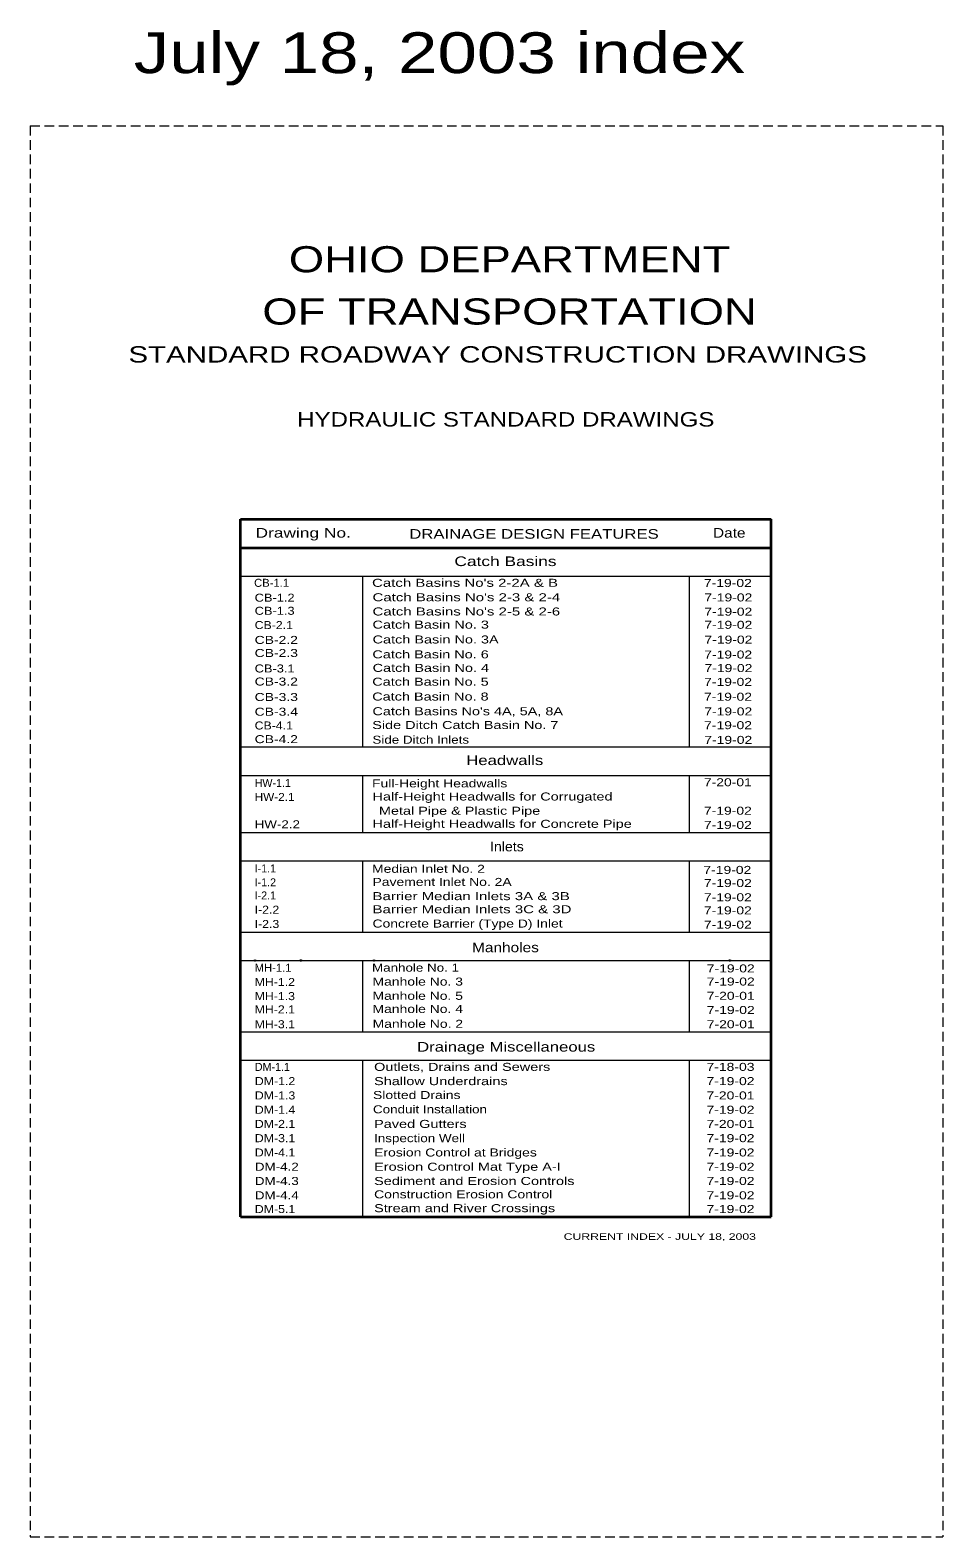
# Model space of a CAD drawing. Extents: x 597.2 to 619.2, y 2097.9 to 2134.2.
import ezdxf
from ezdxf.enums import TextEntityAlignment as Align

# ---------------------------------------------------------------- set-up
doc = ezdxf.new("R2010")
doc.units = 0
doc.header["$LTSCALE"] = 0.077
doc.header["$PDMODE"] = 32
doc.header["$PDSIZE"] = 0.0385
doc.linetypes.add('MEDIUM_DASHED', pattern=[4.5, 3, -1.5])
doc.layers.add('1', color=7, linetype='Continuous', lineweight=13)

msp = doc.modelspace()

# ---------------------------------------------------------------- linework, layer by layer
at = {"layer": '1', "linetype": 'MEDIUM_DASHED'}
for p, q in [((597.168, 2131.89967), (619.168, 2131.89967)), ((597.168, 2131.89967), (597.168, 2097.89967)), ((619.168, 2131.89967), (619.168, 2097.89967)), ((597.168, 2097.89967), (619.168, 2097.89967))]:
    msp.add_line(p, q, dxfattribs=at)
at = {"layer": '1', "lineweight": 35}
for p, q in [((602.237, 2105.61442), (602.237, 2122.41925)), ((602.237, 2122.41925), (615.02575, 2122.41925)), ((615.02575, 2105.61442), (615.02575, 2122.41925)), ((602.23667, 2121.73333), (615.02558, 2121.73333)), ((602.237, 2105.61442), (615.02592, 2105.61442))]:
    msp.add_line(p, q, dxfattribs=at)
at = {"layer": '1'}
for p, q in [((602.23667, 2121.04742), (615.02558, 2121.04742)), ((605.18808, 2116.932), (605.18808, 2121.04742)), ((613.05808, 2116.932), (613.05808, 2121.04742)), ((602.23667, 2116.932), (615.02558, 2116.932)), ((602.23667, 2116.24617), (615.02558, 2116.24617)), ((605.18808, 2114.87225), (605.18808, 2116.24617)), ((613.05808, 2114.87217), (613.05808, 2116.24617)), ((602.23667, 2114.87433), (615.02558, 2114.87433)), ((602.23667, 2114.18842), (615.02558, 2114.18842)), ((602.23667, 2114.18842), (615.02558, 2114.18842)), ((605.18808, 2114.18842), (605.18808, 2114.19175)), ((605.18808, 2112.47275), (605.18808, 2114.18842)), ((613.05808, 2114.18842), (613.05808, 2114.189)), ((613.05808, 2112.47275), (613.05808, 2114.18842)), ((602.23667, 2112.47275), (615.02558, 2112.47275)), ((602.23683, 2111.78683), (615.02558, 2111.78683)), ((605.18808, 2110.07208), (605.18808, 2111.78683)), ((613.05808, 2110.09533), (613.05808, 2111.78683)), ((605.18808, 2110.07208), (605.18808, 2111.10092)), ((613.05808, 2110.07208), (613.05808, 2111.10092)), ((602.23683, 2110.07208), (615.02558, 2110.07208)), ((602.23667, 2109.38617), (615.02558, 2109.38617)), ((605.18808, 2108.01408), (605.18808, 2109.38617)), ((613.05808, 2108.01408), (613.05808, 2109.38617)), ((613.05808, 2106.65533), (613.05808, 2109.36508)), ((605.18808, 2106.11242), (605.18808, 2108.85625)), ((605.18808, 2105.61342), (605.18808, 2106.9855)), ((613.05808, 2105.61342), (613.05808, 2107.00658))]:
    msp.add_line(p, q, dxfattribs=at)
for p in [(602.59033, 2111.78683), (603.69258, 2111.78683), (605.45783, 2111.78683), (614.03458, 2111.78683)]:
    msp.add_point(p, dxfattribs=at)

# ---------------------------------------------------------------- texts
for s, height, width, p in [('July 18, 2003 index', 0.9837, 1.3, (599.66625, 2133.16925)), ('CB-1.1', 0.1928, 1.05, (602.56633, 2120.79133)), ("Catch Basins No's 2-2A & B", 0.1928, 1.4, (605.40933, 2120.79167)), ('7-19-02', 0.1928, 1.3, (613.40775, 2120.78758)), ('CB-1.2', 0.1928, 1.2, (602.57975, 2120.43317)), ("Catch Basins No's 2-3 & 2-4", 0.1928, 1.4, (605.42092, 2120.44383)), ('7-19-02', 0.1928, 1.3, (613.41933, 2120.43975)), ('CB-1.3', 0.1928, 1.2, (602.57975, 2120.11783)), ("Catch Basins No's 2-5 & 2-6", 0.1928, 1.4, (605.42092, 2120.10083)), ('7-19-02', 0.1928, 1.3, (613.41933, 2120.09675)), ('CB-2.1', 0.1928, 1.15, (602.57975, 2119.77392)), ('Catch Basin No. 3', 0.1928, 1.35, (605.42075, 2119.78458)), ('7-19-02', 0.1928, 1.3, (613.41917, 2119.7805)), ('CB-2.2', 0.1928, 1.3, (602.57975, 2119.41575)), ('Catch Basin No. 3A', 0.1928, 1.35, (605.42292, 2119.42642)), ('7-19-02', 0.1928, 1.3, (613.42133, 2119.42233)), ('CB-2.3', 0.1928, 1.3, (602.57975, 2119.10042)), ('Catch Basin No. 6', 0.1928, 1.35, (605.41758, 2119.06808)), ('7-19-02', 0.1928, 1.3, (613.416, 2119.064)), ('CB-3.1', 0.1928, 1.2, (602.57975, 2118.72783)), ('Catch Basin No. 4', 0.1928, 1.35, (605.42358, 2118.74183)), ('7-19-02', 0.1928, 1.3, (613.422, 2118.73775)), ('CB-3.2', 0.1928, 1.3, (602.57975, 2118.41258)), ('Catch Basin No. 5', 0.1928, 1.35, (605.41517, 2118.409)), ('7-19-02', 0.1928, 1.3, (613.41358, 2118.40492)), ('CB-3.3', 0.1928, 1.3, (602.57975, 2118.04)), ('Catch Basin No. 8', 0.1928, 1.35, (605.414, 2118.05142)), ('7-19-02', 0.1928, 1.3, (613.41242, 2118.04733)), ('CB-3.4', 0.1928, 1.3, (602.57975, 2117.68575)), ("Catch Basins No's 4A, 5A, 8A", 0.1928, 1.35, (605.41908, 2117.69717)), ('7-19-02', 0.1928, 1.3, (613.4175, 2117.69308)), ('CB-4.1', 0.1928, 1.15, (602.57975, 2117.35408)), ('Side Ditch Catch Basin No. 7', 0.1928, 1.35, (605.414, 2117.36558)), ('7-19-02', 0.1928, 1.3, (613.41242, 2117.3615)), ('CB-4.2', 0.1928, 1.3, (602.57975, 2117.02458)), ('Side Ditch Inlets', 0.1928, 1.25, (605.41908, 2117.01125)), ('7-19-02', 0.1928, 1.3, (613.4175, 2117.00717)), ('Full-Height Headwalls', 0.1928, 1.3, (605.40933, 2115.95867)), ('7-20-01', 0.1928, 1.3, (613.40775, 2115.98625)), ('HW-2.1', 0.1928, 1.1, (602.57975, 2115.63192)), ('Half-Height Headwalls for Corrugated ', 0.1928, 1.35, (605.42092, 2115.64258)), ('HW-2.2', 0.1928, 1.25, (602.57975, 2114.97367)), ('Half-Height Headwalls for Concrete Pipe', 0.1928, 1.35, (605.42108, 2114.98433)), ('       Metal Pipe & Plastic Pipe', 0.1928, 1.35, (604.8975, 2115.29958)), ('7-19-02', 0.1928, 1.3, (613.40775, 2115.30042)), ('7-19-02', 0.1928, 1.3, (613.40775, 2114.95742)), ('Median Inlet No. 2', 0.1928, 1.3, (605.40933, 2113.901)), ('Pavement Inlet No. 2A', 0.1928, 1.3, (605.42092, 2113.58483)), ('7-19-02', 0.1928, 1.3, (613.396, 2113.87408)), ('7-19-02', 0.1928, 1.3, (613.40758, 2113.55792)), ('Barrier Median Inlets 3A & 3B', 0.1928, 1.4, (605.42092, 2113.24192)), ('7-19-02', 0.1928, 1.3, (613.40758, 2113.215)), ('I-2.2', 0.1928, 1.15, (602.57975, 2112.915)), ('Barrier Median Inlets 3C & 3D', 0.1928, 1.4, (605.42075, 2112.92567)), ('7-19-02', 0.1928, 1.3, (613.40742, 2112.89875)), ('I-2.3', 0.1928, 1.15, (602.57975, 2112.571)), ('Concrete Barrier (Type D) Inlet', 0.1928, 1.3, (605.42075, 2112.58175)), ('7-19-02', 0.1928, 1.3, (613.40742, 2112.55483)), ('MH-1.1', 0.1928, 1.05, (602.57975, 2111.51592)), ('Manhole No. 1', 0.1928, 1.25, (605.40933, 2111.51875)), ('7-19-02', 0.1928, 1.3, (613.47758, 2111.50083)), ('MH-1.2', 0.1928, 1.15, (602.57975, 2111.17258)), ('Manhole No. 3', 0.1928, 1.3, (605.42092, 2111.18325)), ('7-19-02', 0.1928, 1.3, (613.47758, 2111.18408)), ('MH-1.3', 0.1928, 1.15, (602.57975, 2110.83258)), ('Manhole No. 5', 0.1928, 1.3, (605.42092, 2110.84033)), ('7-20-01', 0.1928, 1.3, (613.47758, 2110.84108)), ('MH-2.1', 0.1928, 1.15, (602.57975, 2110.51333)), ('Manhole No. 4', 0.1928, 1.3, (605.42075, 2110.524)), ('7-19-02', 0.1928, 1.3, (613.47758, 2110.49817)), ('MH-3.1', 0.1928, 1.15, (602.57975, 2110.15517)), ('Manhole No. 2', 0.1928, 1.3, (605.42292, 2110.16583)), ('7-20-01', 0.1928, 1.3, (613.47758, 2110.15517)), ('Outlets, Drains and Sewers', 0.1933, 1.35, (605.45875, 2109.12783)), ('7-18-03', 0.1933, 1.3, (613.46958, 2109.12783)), ('DM-1.2', 0.1933, 1.15, (602.58383, 2108.78458)), ('DM-1.3', 0.1933, 1.15, (602.58383, 2108.43967)), ('Slotted Drains', 0.1933, 1.3, (605.43217, 2108.45025)), ('Shallow Underdrains', 0.1933, 1.35, (605.45875, 2108.78458)), ('7-19-02', 0.1933, 1.3, (613.46958, 2108.78458)), ('7-20-01', 0.1933, 1.3, (613.46958, 2108.43967)), ('DM-1.4', 0.1933, 1.15, (602.58383, 2108.09475)), ('Conduit Installation', 0.1933, 1.25, (605.43217, 2108.10533)), ('7-19-02', 0.1933, 1.3, (613.46958, 2108.09475)), ('DM-2.1', 0.1933, 1.15, (602.58383, 2107.75317)), ('Paved Gutters', 0.1933, 1.35, (605.45875, 2107.75317)), ('7-20-01', 0.1933, 1.3, (613.46958, 2107.75317)), ('DM-3.1', 0.1933, 1.15, (602.58383, 2107.40992)), ('Inspection Well', 0.1933, 1.25, (605.45875, 2107.40992)), ('7-19-02', 0.1933, 1.3, (613.46958, 2107.40992)), ('DM-4.1', 0.1933, 1.15, (602.58383, 2107.06492)), ('Erosion Control at Bridges', 0.1933, 1.3, (605.45875, 2107.06492)), ('7-19-02', 0.1933, 1.3, (613.46958, 2107.06492)), ('DM-4.2', 0.1933, 1.25, (602.58383, 2106.72175)), ('Erosion Control Mat Type A-I', 0.1933, 1.35, (605.45875, 2106.72175)), ('7-19-02', 0.1933, 1.3, (613.46958, 2106.72175)), ('DM-4.3', 0.1933, 1.25, (602.58383, 2106.3785)), ('Sediment and Erosion Controls', 0.1933, 1.35, (605.45875, 2106.3785)), ('7-19-02', 0.1933, 1.3, (613.46958, 2106.3785)), ('DM-4.4', 0.1933, 1.25, (602.58383, 2106.0335)), ('Construction Erosion Control', 0.1933, 1.3, (605.45875, 2106.0565)), ('7-19-02', 0.1933, 1.3, (613.46958, 2106.0335)), ('DM-5.1', 0.1933, 1.15, (602.58383, 2105.70208)), ('Stream and River Crossings', 0.1933, 1.35, (605.45875, 2105.72333)), ('7-19-02', 0.1933, 1.3, (613.46958, 2105.70208))]:
    msp.add_text(s, height=height, dxfattribs=dict(at, width=width)).set_placement(p)
for s, height, width, p in [('OHIO DEPARTMENT', 0.6296, 1.3, (608.72371, 2128.36975)), ('OF TRANSPORTATION', 0.6296, 1.3, (608.72383, 2127.11075)), ('STANDARD ROADWAY CONSTRUCTION DRAWINGS', 0.3935, 1.35, (608.43679, 2126.19558)), ('HYDRAULIC STANDARD DRAWINGS', 0.3471, 1.25, (608.63212, 2124.65308)), ('Drawing No.', 0.2314, 1.35, (603.75004, 2121.9765)), ('DRAINAGE DESIGN FEATURES', 0.2314, 1.3, (609.31304, 2121.95058)), ('Date', 0.2314, 1.2, (614.01912, 2121.9765)), ('Catch Basins', 0.2314, 1.35, (608.62517, 2121.29175)), ('Headwalls', 0.2314, 1.3, (608.60796, 2116.49658)), ('Inlets', 0.2314, 1.1, (608.65963, 2114.41733)), ('Manholes', 0.2314, 1.2, (608.62517, 2111.98675)), ('Drainage Miscellaneous', 0.2314, 1.3, (608.64242, 2109.59208)), ('CURRENT INDEX - JULY 18, 2003', 0.1574, 1.4, (612.34525, 2105.05642))]:
    msp.add_text(s, height=height, dxfattribs=dict(at, width=width)).set_placement(p, align=Align.CENTER)
for s, height, p in [('HW-1.1', 0.1928, (602.57975, 2115.9675)), ('I-1.1', 0.1928, (602.57975, 2113.90983)), ('I-1.2', 0.1928, (602.57975, 2113.57417)), ('I-2.1', 0.1928, (602.57975, 2113.25892)), ('DM-1.1', 0.1933, (602.58383, 2109.12783))]:
    msp.add_text(s, height=height, dxfattribs=at).set_placement(p)

doc.saveas('drawing.dxf')
